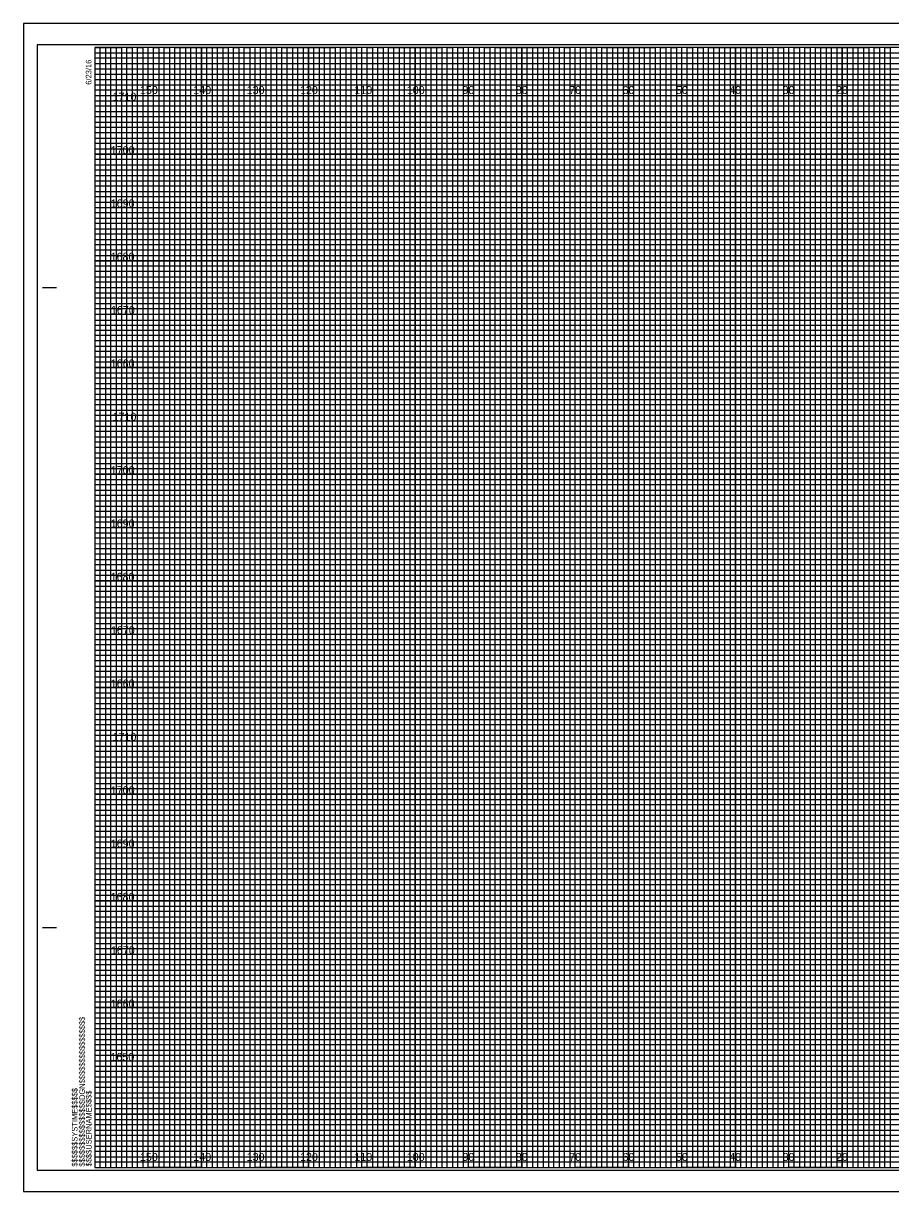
# Model space of a CAD drawing. Extents: x -13 to 323, y -5 to 2414.
# Drawn here: x -13.4 to 149.1, y 1755.5 to 1974.5 of the extents above; entities that cross this region are included whole.
import ezdxf

# ---------------------------------------------------------------- set-up
doc = ezdxf.new("R2010")
doc.units = 0
for name, color, linetype in [('Prop XS Elevation Labels', 7, 'Continuous'), ('Prop XS Offset Labels', 7, 'Continuous'), ('Sheet Cross Section CELL', 7, 'Continuous'), ('Sheet Cross Section Grid Major CELL', 7, 'Continuous'), ('Sheet Cross Section Grid Middle CELL', 7, 'Continuous'), ('Sheet Cross Section Grid Minor 1 CELL', 7, 'Continuous'), ('Sheet Cross Section Grid Minor 2 CELL', 7, 'Continuous'), ('Sheet Cutting Line CELL', 7, 'Continuous'), ('Sheet DOT Grid CELL', 7, 'Continuous'), ('Sheet Plot Border Inside CELL', 7, 'Continuous'), ('Sheet Plot Border Outside CELL', 7, 'Continuous')]:
    doc.layers.add(name, color=color, linetype=linetype)

msp = doc.modelspace()

# ---------------------------------------------------------------- linework, layer by layer
at = {"layer": 'Sheet Cross Section CELL'}
for p, q in [((-9.8, 1925), (-7.3, 1925)), ((-9.7, 1925), (-7.2, 1925)), ((-9.8, 1805), (-7.3, 1805)), ((-9.7, 1805), (-7.2, 1805)), ((0, 1760), (0, 1760)), ((0, 1760), (0, 1760)), ((0, 1760), (0, 1760)), ((0, 1760), (0, 1760)), ((0, 1760), (0, 1760)), ((0, 1760), (0, 1760)), ((0, 1760), (0, 1760))]:
    msp.add_line(p, q, dxfattribs=at)
msp.add_lwpolyline([(320, 1970), (0, 1970), (0, 1760), (320, 1760)], close=True, dxfattribs=at)
at = {"layer": 'Sheet Cross Section Grid Major CELL'}
for p, q in [((10, 1970), (0, 1970)), ((10, 1760), (10, 1970)), ((30, 1970), (20, 1970)), ((20, 1970), (20, 1760)), ((30, 1760), (30, 1970)), ((50, 1970), (40, 1970)), ((40, 1970), (40, 1760)), ((50, 1760), (50, 1970)), ((70, 1970), (60, 1970)), ((60, 1970), (60, 1760)), ((70, 1760), (70, 1970)), ((90, 1970), (80, 1970)), ((80, 1970), (80, 1760)), ((90, 1760), (90, 1970)), ((110, 1970), (100, 1970)), ((100, 1970), (100, 1760)), ((110, 1760), (110, 1970)), ((130, 1970), (120, 1970)), ((120, 1970), (120, 1760)), ((130, 1760), (130, 1970)), ((150, 1970), (140, 1970)), ((140, 1970), (140, 1760)), ((20, 1760), (10, 1760)), ((40, 1760), (30, 1760)), ((60, 1760), (50, 1760)), ((80, 1760), (70, 1760)), ((100, 1760), (90, 1760)), ((120, 1760), (110, 1760)), ((140, 1760), (130, 1760))]:
    msp.add_line(p, q, dxfattribs=at)
for points in [[(0, 1960), (320, 1960), (320, 1950), (0, 1950)], [(0, 1940), (320, 1940), (320, 1930), (0, 1930)], [(0, 1920), (320, 1920), (320, 1910), (0, 1910)], [(0, 1900), (320, 1900), (320, 1890), (0, 1890)], [(0, 1880), (320, 1880), (320, 1870), (0, 1870)], [(0, 1860), (320, 1860), (320, 1850), (0, 1850)], [(0, 1840), (320, 1840), (320, 1830), (0, 1830)], [(0, 1820), (320, 1820), (320, 1810), (0, 1810)], [(0, 1800), (320, 1800), (320, 1790), (0, 1790)], [(0, 1780), (320, 1780), (320, 1770), (0, 1770)]]:
    msp.add_lwpolyline(points, dxfattribs=at)
at = {"layer": 'Sheet Cross Section Grid Middle CELL'}
for points in [[(0, 1970), (5, 1970), (5, 1760), (15, 1760), (15, 1970), (25, 1970), (25, 1760), (35, 1760), (35, 1970), (45, 1970), (45, 1760), (55, 1760), (55, 1970), (65, 1970), (65, 1760), (75, 1760), (75, 1970), (85, 1970), (85, 1760), (95, 1760), (95, 1970), (105, 1970), (105, 1760), (115, 1760), (115, 1970), (125, 1970), (125, 1760), (135, 1760), (135, 1970), (145, 1970), (145, 1760), (155, 1760)], [(0, 1965), (275, 1965)], [(0, 1945), (320, 1945), (320, 1955), (0, 1955)], [(0, 1925), (320, 1925), (320, 1935), (0, 1935)], [(0, 1905), (320, 1905), (320, 1915), (0, 1915)], [(0, 1885), (320, 1885), (320, 1895), (0, 1895)], [(0, 1865), (320, 1865), (320, 1875), (0, 1875)], [(0, 1845), (320, 1845), (320, 1855), (0, 1855)], [(0, 1825), (320, 1825), (320, 1835), (0, 1835)], [(0, 1805), (320, 1805), (320, 1815), (0, 1815)], [(0, 1785), (320, 1785), (320, 1795), (0, 1795)], [(0, 1765), (320, 1765), (320, 1775), (0, 1775)]]:
    msp.add_lwpolyline(points, dxfattribs=at)
at = {"layer": 'Sheet Cross Section Grid Minor 1 CELL'}
for p, q in [((0, 1969), (260, 1969)), ((260, 1967.98), (0, 1967.98)), ((0, 1967.98), (0, 1967)), ((0, 1967), (260, 1967)), ((260, 1965.89), (0, 1965.89)), ((0, 1965.89), (0, 1964)), ((0, 1964), (320, 1964))]:
    msp.add_line(p, q, dxfattribs=at)
for points in [[(0, 1963), (270, 1963), (320, 1963), (320, 1962), (0, 1962)], [(0, 1961), (320, 1961), (320, 1959), (0, 1959)], [(0, 1958), (320, 1958), (320, 1957), (0, 1956.98)], [(0, 1956), (320, 1956), (320, 1954), (0, 1954)], [(0, 1953), (320, 1953), (320, 1952), (0, 1952)], [(0, 1951), (320, 1951), (320, 1949), (0, 1949)], [(0, 1948), (320, 1948), (320, 1947), (0, 1947)], [(0, 1946), (320, 1946), (320, 1944), (0, 1944)], [(0, 1943), (320, 1943), (320, 1942), (0, 1942)], [(0, 1941), (320, 1941), (320, 1939), (0, 1939)], [(0, 1938), (320, 1938), (320, 1937), (0, 1937)], [(0, 1936), (320, 1936), (320, 1933.95), (320, 1933), (320, 1932), (0, 1932)], [(0, 1934), (320, 1934), (320, 1933), (0, 1933)], [(0, 1931), (320, 1931), (320, 1929), (0, 1929.03)], [(0, 1929.03), (320, 1929), (320, 1928), (0, 1928)], [(0, 1927), (320, 1927), (320, 1926), (0, 1926)], [(0, 1924), (320, 1924), (320, 1923), (0, 1923)], [(0, 1922), (320, 1922), (320, 1921), (0, 1921)], [(-0.07, 1918.89), (320, 1918.89), (320, 1917.88), (-0.07, 1917.88)], [(0, 1917), (320, 1917), (320, 1916), (0, 1916)], [(0, 1914), (320, 1914), (320, 1913), (0, 1913)], [(0, 1912), (320, 1912), (320, 1911), (0, 1911)], [(0, 1909), (320, 1909), (320, 1908), (0, 1908)], [(0, 1907), (320, 1907), (320, 1906), (0, 1906)], [(0, 1904), (320, 1904), (320, 1903), (0, 1903)], [(0, 1902), (320, 1902), (320, 1901), (0, 1901)], [(0, 1899), (320, 1899), (319.99, 1897.98), (0, 1898)], [(0, 1897), (320, 1897), (320, 1896), (0, 1896)], [(0, 1894), (320, 1894), (320, 1893), (0, 1893)], [(0, 1892), (320, 1892), (320, 1891), (0, 1891)], [(0, 1889), (320, 1889), (320, 1888), (0, 1888)], [(0, 1887), (320, 1887), (320, 1886), (0, 1886)], [(0, 1884), (320, 1884), (320, 1883), (0, 1883)], [(0, 1882), (320, 1882), (320, 1881), (0, 1881)], [(0, 1879), (320, 1879), (320, 1878), (0, 1878)], [(0, 1876.99), (320.07, 1876.91), (320, 1876), (0, 1876)], [(0, 1874), (320, 1874), (320, 1873), (0, 1873)], [(0, 1872), (320, 1872), (320, 1871), (0, 1871)], [(0, 1869), (320, 1869), (320, 1868), (0, 1868)], [(0, 1867), (320, 1867), (320, 1866), (0, 1866)], [(0, 1864), (320, 1864), (320, 1863), (0, 1863)], [(0, 1862), (320, 1862), (320, 1861), (0, 1861)], [(0, 1859), (320, 1859), (320, 1858), (0, 1858)], [(0, 1857), (320, 1857), (320, 1856), (0, 1856)], [(0, 1854), (320, 1854), (320, 1853), (0, 1853)], [(0, 1852), (320, 1852), (320, 1851), (0, 1851)], [(0, 1849), (320, 1849), (320, 1848), (0, 1848)], [(0, 1847), (320, 1847), (320, 1846), (0, 1846)], [(0, 1844), (320, 1844), (320, 1843), (0, 1843)], [(0, 1842), (320, 1842), (320, 1841), (0, 1841)], [(0, 1839), (320, 1839), (319.99, 1837.98), (0, 1838)], [(0, 1837), (320, 1837), (320, 1836), (0, 1836)], [(0, 1834), (320, 1834), (320, 1833), (0, 1833)], [(0, 1832), (320, 1832), (320, 1831), (0, 1831)], [(0, 1829), (320, 1829), (320, 1828), (0, 1828)], [(0, 1827), (320, 1827), (320, 1826), (0, 1826)], [(0, 1824), (320, 1824), (320, 1823), (0, 1823)], [(0, 1822), (320, 1822), (320, 1821), (0, 1821)], [(0, 1819), (320, 1819), (320, 1818), (0, 1818)], [(0, 1816.99), (320.07, 1816.91), (320, 1816), (0, 1816)], [(0, 1814), (320, 1814), (320, 1813), (0, 1813)], [(0, 1812), (320, 1812), (320, 1811), (0, 1811)], [(0, 1809), (320, 1809), (320, 1808), (0, 1808)], [(0, 1807), (320, 1807), (320, 1806), (0, 1806)], [(0, 1804), (320, 1804), (320, 1803), (0, 1803)], [(0, 1802), (320, 1802), (320, 1801), (0, 1801)], [(0, 1799), (320, 1799), (320, 1798), (0, 1798)], [(0, 1797), (320, 1797), (320, 1796), (0, 1796)], [(0, 1794), (320, 1794), (320, 1793), (0, 1793)], [(0, 1792), (320, 1792), (320, 1791), (0, 1791)], [(0, 1789), (320, 1789), (320, 1788), (0, 1788)], [(0, 1787), (320, 1787), (320, 1786), (0, 1786)], [(0, 1784), (320, 1784), (320, 1783), (0, 1783)], [(0, 1782), (320, 1782), (320, 1781), (0, 1781)], [(0, 1779), (320, 1779), (320, 1778), (0, 1778)], [(0, 1777), (320, 1777), (320, 1776), (0, 1776)], [(0, 1774), (320, 1774), (320, 1773), (0, 1773)], [(0, 1772), (320, 1772), (320, 1771), (0, 1771)], [(0, 1769), (320, 1769), (320, 1768), (0, 1768)], [(0, 1767), (320, 1767), (320, 1766), (0, 1766)], [(0, 1764), (320, 1764), (320, 1763), (0, 1763)], [(0, 1762), (320, 1762), (320, 1761), (0, 1761)]]:
    msp.add_lwpolyline(points, dxfattribs=at)
at = {"layer": 'Sheet Cross Section Grid Minor 2 CELL'}
for points in [[(0, 1760), (1, 1760), (1, 1970), (2, 1970), (2, 1760)], [(2, 1760), (3, 1760), (3, 1970), (4, 1970), (4, 1760)], [(5, 1760), (6, 1760), (6, 1970), (7, 1970), (7, 1760)], [(7, 1760), (8, 1760), (8, 1970), (9, 1970), (9, 1760)], [(10, 1760), (11, 1760), (11, 1970), (12, 1970), (12, 1760)], [(12, 1760), (13, 1760), (13, 1970), (14, 1970), (14, 1760)], [(15, 1760), (16, 1760), (16, 1970), (17, 1970), (17, 1760)], [(17, 1760), (18, 1760), (18, 1970), (19, 1970), (19, 1760)], [(20, 1760), (21, 1760), (21, 1970), (22, 1970), (22, 1760)], [(22, 1760), (23, 1760), (23, 1970), (24, 1970), (24, 1760)], [(25, 1760), (26, 1760), (26, 1970), (27, 1970), (27, 1760)], [(27, 1760), (28, 1760), (28, 1970), (29, 1970), (29, 1760)], [(30, 1760), (31, 1760), (31, 1970), (32, 1970), (32, 1760)], [(32, 1760), (33, 1760), (33, 1970), (34, 1970), (34, 1760)], [(35, 1760), (36, 1760), (36, 1970), (37, 1970), (37, 1760)], [(37, 1760), (38, 1760), (38, 1970), (39, 1970), (39, 1760)], [(40, 1760), (41, 1760), (41, 1970), (42, 1970), (42, 1760)], [(42, 1760), (43, 1760), (43, 1970), (44, 1970), (44, 1760)], [(45, 1760), (46, 1760), (46, 1970), (47, 1970), (47, 1760)], [(47, 1760), (48, 1760), (48, 1970), (49, 1970), (49, 1760)], [(50, 1760), (51, 1760), (51, 1970), (52, 1970), (52, 1760)], [(52, 1760), (53, 1760), (53, 1970), (54, 1970), (54, 1760)], [(55, 1760), (56, 1760), (56, 1970), (57, 1970), (57, 1760)], [(57, 1760), (58, 1760), (58, 1970), (59, 1970), (59, 1760)], [(60, 1760), (61, 1760), (61, 1970), (62, 1970), (62, 1760)], [(62, 1760), (63, 1760), (63, 1970), (64, 1970), (64, 1760)], [(65, 1760), (66, 1760), (66, 1970), (67, 1970), (67, 1760)], [(67, 1760), (68, 1760), (68, 1970), (69, 1970), (69, 1760)], [(70, 1760), (71, 1760), (71, 1970), (72, 1970), (72, 1760)], [(72, 1760), (73, 1760), (73, 1970), (74, 1970), (74, 1760)], [(75, 1760), (76, 1760), (76, 1970), (77, 1970), (77, 1760)], [(77, 1760), (78, 1760), (78, 1970), (79, 1970), (79, 1760)], [(80, 1760), (81, 1760), (81, 1970), (82, 1970), (82, 1760)], [(82, 1760), (83, 1760), (83, 1970), (84, 1970), (84, 1760)], [(85, 1760), (86, 1760), (86, 1970), (87, 1970), (87, 1760)], [(87, 1760), (88, 1760), (88, 1970), (89, 1970), (89, 1760)], [(90, 1760), (91, 1760), (91, 1970), (92, 1970), (92, 1760)], [(92, 1760), (93, 1760), (93, 1970), (94, 1970), (94, 1760)], [(95, 1760), (96, 1760), (96, 1970), (97, 1970), (97, 1760)], [(97, 1760), (98, 1760), (98, 1970), (99, 1970), (99, 1760)], [(100, 1760), (101, 1760), (101, 1970), (102, 1970), (102, 1760)], [(102, 1760), (103, 1760), (103, 1970), (104, 1970), (104, 1760)], [(105, 1760), (106, 1760), (106, 1970), (107, 1970), (107, 1760)], [(107, 1760), (108, 1760), (108, 1970), (109, 1970), (109, 1760)], [(110, 1760), (111, 1760), (111, 1970), (112, 1970), (112, 1760)], [(112, 1760), (113, 1760), (113, 1970), (114, 1970), (114, 1760)], [(115, 1760), (116, 1760), (116, 1970), (117, 1970), (117, 1760)], [(117, 1760), (118, 1760), (118, 1970), (119, 1970), (119, 1760)], [(120, 1760), (121, 1760), (121, 1970), (122, 1970), (122, 1760)], [(122, 1760), (123, 1760), (123, 1970), (124, 1970), (124, 1760)], [(125, 1760), (126, 1760), (126, 1970), (127, 1970), (127, 1760)], [(127, 1760), (128, 1760), (128, 1970), (129, 1970), (129, 1760)], [(130, 1760), (131, 1760), (131, 1970), (132, 1970), (132, 1760)], [(132, 1760), (133, 1760), (133, 1970), (134, 1970), (134, 1760)], [(135, 1760), (136, 1760), (136, 1970), (137, 1970), (137, 1760)], [(137, 1760), (138, 1760), (138, 1970), (139, 1970), (139, 1760)], [(140, 1760), (141, 1760), (141, 1970), (142, 1970), (142, 1760)], [(142, 1760), (143, 1760), (143, 1970), (144, 1970), (144, 1760)], [(145, 1760), (146, 1760), (146, 1970), (147, 1970), (147, 1760)], [(147, 1760), (148, 1760), (148, 1970), (149, 1970), (149, 1760)]]:
    msp.add_lwpolyline(points, dxfattribs=at)
at = {"layer": 'Sheet Cutting Line CELL'}
for p, q in [((323.3, 1974.5), (-13.4, 1974.5)), ((-13.4, 1974.5), (-13.4, 1755.5)), ((-13.4, 1755.5), (323.3, 1755.5))]:
    msp.add_line(p, q, dxfattribs=at)
at = {"layer": 'Sheet DOT Grid CELL'}
for p, q in [((10, 1760), (10, 1970)), ((20, 1760), (20, 1970)), ((30, 1760), (30, 1970)), ((40, 1760), (40, 1970)), ((50, 1760), (50, 1970)), ((60, 1760), (60, 1970)), ((70, 1760), (70, 1970)), ((80, 1760), (80, 1970)), ((90, 1760), (90, 1970)), ((100, 1760), (100, 1970)), ((110, 1760), (110, 1970)), ((120, 1760), (120, 1970)), ((130, 1760), (130, 1970)), ((140, 1760), (140, 1970)), ((0, 1960), (320, 1960)), ((0, 1950), (320, 1950)), ((0, 1940), (320, 1940)), ((0, 1930), (320, 1930)), ((0, 1920), (320, 1920)), ((0, 1910), (320, 1910)), ((0, 1900), (320, 1900)), ((0, 1890), (320, 1890)), ((0, 1880), (320, 1880)), ((0, 1870), (320, 1870)), ((0, 1860), (320, 1860)), ((0, 1850), (320, 1850)), ((0, 1840), (320, 1840)), ((0, 1830), (320, 1830)), ((0, 1820), (320, 1820)), ((0, 1810), (320, 1810)), ((0, 1800), (320, 1800)), ((0, 1790), (320, 1790)), ((0, 1780), (320, 1780)), ((0, 1770), (320, 1770))]:
    msp.add_line(p, q, dxfattribs=at)
at = {"layer": 'Sheet Plot Border Inside CELL'}
msp.add_lwpolyline([(-10.8, 1759.5), (322.4, 1759.5), (322.4, 1970.5), (-10.8, 1970.5)], close=True, dxfattribs=at)
at = {"layer": 'Sheet Plot Border Outside CELL'}
msp.add_lwpolyline([(-13.4, 1755.5), (323.3, 1755.5), (323.3, 1974.5), (-13.4, 1974.5)], close=True, dxfattribs=at)

# ---------------------------------------------------------------- texts
at = {"layer": 'Prop XS Elevation Labels'}
for s, p in [('1710', (3.31, 1960)), ('1700', (2.98, 1950)), ('1690', (2.97, 1940)), ('1680', (2.95, 1930)), ('1670', (3, 1920)), ('1660', (2.97, 1910)), ('1710', (3.31, 1900)), ('1700', (2.98, 1890)), ('1690', (2.97, 1880)), ('1680', (2.95, 1870)), ('1670', (3, 1860)), ('1660', (2.97, 1850)), ('1710', (3.31, 1840)), ('1700', (2.98, 1830)), ('1690', (2.97, 1820)), ('1680', (2.95, 1810)), ('1670', (3, 1800)), ('1660', (2.97, 1790)), ('1650', (2.92, 1780))]:
    msp.add_text(s, height=1.5, dxfattribs=at).set_placement(p)
at = {"layer": 'Prop XS Offset Labels'}
for s, p in [('150', (8.44, 1961.25)), ('140', (18.44, 1961.25)), ('130', (28.44, 1961.25)), ('120', (38.44, 1961.25)), ('110', (48.62, 1961.25)), ('100', (58.44, 1961.25)), ('90', (68.86, 1961.25)), ('80', (78.86, 1961.25)), ('70', (88.86, 1961.25)), ('60', (98.86, 1961.25)), ('50', (108.86, 1961.25)), ('40', (118.86, 1961.25)), ('30', (128.86, 1961.25)), ('20', (138.86, 1961.25)), ('150', (8.44, 1761.25)), ('140', (18.44, 1761.25)), ('130', (28.44, 1761.25)), ('120', (38.44, 1761.25)), ('110', (48.62, 1761.25)), ('100', (58.44, 1761.25)), ('90', (68.86, 1761.25)), ('80', (78.86, 1761.25)), ('70', (88.86, 1761.25)), ('60', (98.86, 1761.25)), ('50', (108.86, 1761.25)), ('40', (118.86, 1761.25)), ('30', (128.86, 1761.25)), ('20', (138.86, 1761.25))]:
    msp.add_text(s, height=1.5, dxfattribs=at).set_placement(p)
at = {"layer": 'Sheet Cross Section CELL'}
for s, p in [('6/23/16', (-0.65, 1963)), ('$$$$$$$$$$$$$$$$DGN$$$$$$$$$$$$$$$$', (-1.88, 1760.18)), ('$$$$$$SYSTIME$$$$$', (-3.26, 1760.18)), ('$$$$USERNAME$$$$', (-0.62, 1760.23))]:
    msp.add_text(s, height=1.05, rotation=90, dxfattribs=at).set_placement(p)

doc.saveas('drawing.dxf')
